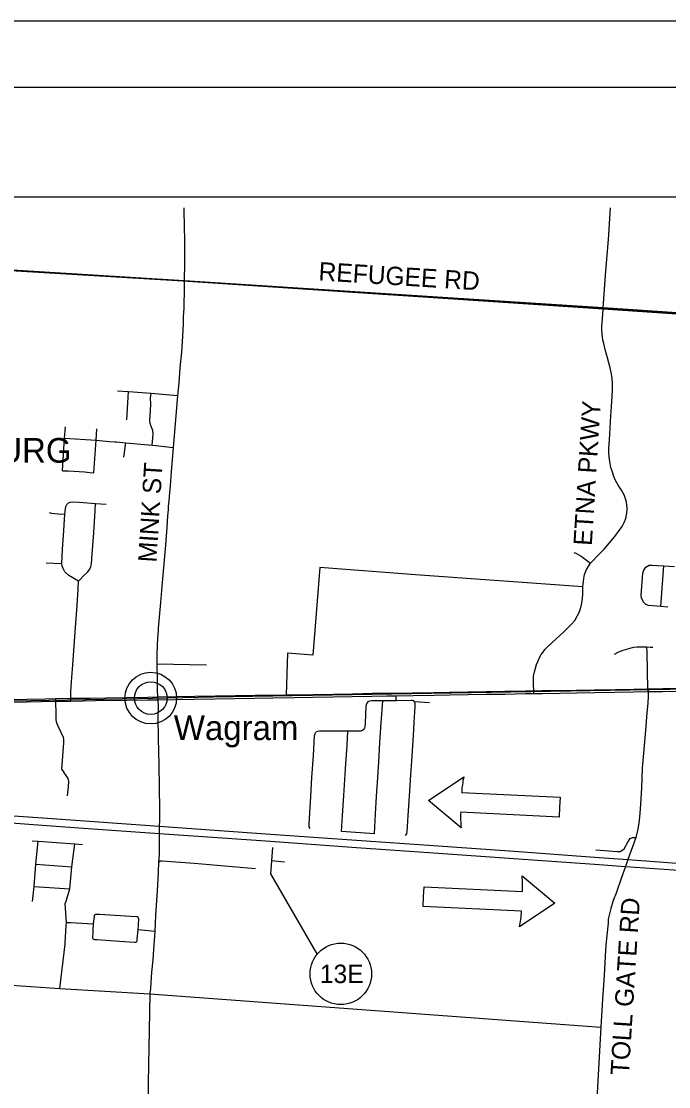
# Model space of a CAD drawing. Extents: x 1880545 to 1948545, y 79309 to 723051.
# Drawn here: x 1901899 to 1911747, y 706837 to 723051 of the extents above; entities that cross this region are included whole.
import ezdxf

# ---------------------------------------------------------------- set-up
doc = ezdxf.new("R2010")
doc.units = 0
for name, color, linetype in [('GM_X_Corporation', 7, 'Continuous'), ('GM_X_Corporation_Text', 7, 'Continuous'), ('GM_X_County_Road', 7, 'Continuous'), ('GM_X_Interstate_Route', 7, 'Continuous'), ('GM_X_Rail_Line', 7, 'Continuous'), ('GM_X_Township', 7, 'Continuous'), ('GM_X_Township_Road', 7, 'Continuous'), ('GM_X_Unincorporated', 7, 'Continuous'), ('GM_X_Unincorporated_Location', 7, 'Continuous'), ('GM_X_Unincorporated_Text', 7, 'Continuous'), ('GM_X_US_Route', 7, 'Continuous'), ('SH_Border', 7, 'Continuous'), ('SH_Cut_Line', 7, 'Continuous'), ('SH_Text', 7, 'Continuous')]:
    doc.layers.add(name, color=color, linetype=linetype)

msp = doc.modelspace()

# ---------------------------------------------------------------- linework, layer by layer
at = {"layer": 'GM_X_Corporation'}
msp.add_lwpolyline([(1919489, 720212), (1919365, 718089), (1918485, 718152), (1917525, 718232), (1914097, 718433), (1913810, 718462), (1910748, 718668), (1904355, 719098), (1898180, 719469), (1898145, 719477), (1897456, 719507), (1897439, 719506), (1897486, 720212)], dxfattribs=at)
at = {"layer": 'GM_X_County_Road'}
for points in [[(1904372, 720212), (1904373, 720143), (1904376, 719959), (1904380, 719685), (1904379, 719381), (1904378, 719096)], [(1904378, 719096), (1904377, 718914), (1904372, 718772), (1904370, 718687), (1904363, 718552), (1904359, 718449), (1904354, 718351), (1904344, 718172), (1904334, 718017), (1904312, 717776), (1904295, 717547), (1904276, 717358), (1904235, 716864), (1904211, 716564), (1904180, 716192), (1904161, 715980), (1904154, 715886), (1904148, 715813), (1904142, 715748), (1904135, 715674), (1904132, 715615), (1904124, 715524), (1904110, 715349), (1904100, 715213), (1904090, 715077), (1904082, 714967), (1904062, 714741), (1904037, 714449), (1904016, 714204), (1903986, 713870), (1903981, 713817), (1903978, 713770), (1903975, 713733), (1903970, 713647), (1903965, 713573), (1903963, 713522), (1903961, 713443), (1903960, 713361), (1903960, 713309), (1903960, 713270), (1903965, 713041), (1903966, 712877), (1903969, 712770), (1903973, 712727)], [(1903973, 712727), (1903978, 712618), (1903977, 712471), (1903979, 712132), (1903987, 711942), (1903993, 711730), (1903998, 711397), (1904003, 711057), (1904000, 710886), (1903998, 710801), (1903996, 710690), (1903994, 710365), (1903987, 710253), (1903980, 710101), (1903964, 709817), (1903941, 709446), (1903928, 709201), (1903905, 708856), (1903899, 708769), (1903881, 708580), (1903865, 708338), (1903856, 708249), (1903839, 707422), (1903835, 707192), (1903824, 706540)]]:
    msp.add_lwpolyline(points, dxfattribs=at)
at = {"layer": 'GM_X_Interstate_Route'}
for points in [[(1901417, 710877), (1902079, 710829), (1902917, 710765), (1903996, 710690), (1905616, 710577), (1906997, 710477), (1908167, 710395), (1909393, 710308), (1910617, 710222), (1911089, 710188), (1911973, 710126), (1913517, 710014), (1914784, 709928), (1915690, 709872), (1916454, 709820), (1916505, 709817), (1917219, 709770)], [(1901556, 710973), (1902367, 710916), (1903998, 710801), (1905618, 710687), (1906999, 710588), (1908169, 710506), (1909395, 710419), (1910619, 710332), (1911124, 710293), (1912007, 710228), (1913551, 710117), (1914818, 710030), (1915724, 709975), (1916510, 709920), (1917291, 709874), (1917321, 709872), (1918107, 709817), (1919464, 709729), (1920634, 709656), (1921054, 709629)]]:
    msp.add_lwpolyline(points, dxfattribs=at)
at = {"layer": 'GM_X_Rail_Line'}
msp.add_lwpolyline([(1889656, 712431), (1890757, 712458), (1898417, 712647), (1903434, 712741), (1904816, 712771), (1913576, 712916), (1914801, 712916), (1920019, 712995), (1921942, 713063), (1924553, 713124), (1928206, 713206)], dxfattribs=at)
at = {"layer": 'GM_X_Township'}
for points in [[(1919533, 720212), (1919387, 718085), (1918485, 718152), (1917525, 718232), (1914126, 718466), (1913826, 718485), (1910749, 718688), (1904377, 719099), (1899877, 719378), (1898145, 719477), (1897456, 719507), (1896834, 719533), (1896793, 719532), (1894775, 719644), (1893522, 719763), (1893081, 719771), (1891817, 719823), (1891843, 720212)], [(1899877, 719378), (1904377, 719099), (1910749, 718688), (1913826, 718485), (1914126, 718466), (1917525, 718232), (1918485, 718152), (1919387, 718085), (1922041, 717966)]]:
    msp.add_lwpolyline(points, dxfattribs=at)
at = {"layer": 'GM_X_Township_Road'}
for p, q in [((1903502, 716987), (1903529, 717418)), ((1903458, 716418), (1903491, 716637)), ((1902278, 714808), (1902514, 714797)), ((1911627, 714145), (1911672, 714765)), ((1903960, 713270), (1904715, 713258)), ((1907599, 712710), (1907600, 712786)), ((1907269, 710685), (1906771, 710721)), ((1902122, 710223), (1902665, 710182)), ((1902094, 709882), (1902639, 709846)), ((1903856, 708249), (1910713, 707744)), ((1910713, 707744), (1910640, 706422))]:
    msp.add_line(p, q, dxfattribs=at)
for points in [[(1910750, 718685), (1910787, 719189), (1910830, 719731), (1910864, 720212)], [(1904378, 719096), (1899878, 719375), (1898146, 719475)], [(1913827, 718483), (1910750, 718685), (1904378, 719096)], [(1909693, 712821), (1909693, 712863), (1909692, 712963), (1909691, 713086), (1909703, 713152), (1909721, 713208), (1909737, 713261), (1909760, 713319), (1909787, 713378), (1909808, 713415), (1909835, 713452), (1909865, 713489), (1909909, 713535), (1910152, 713760), (1910214, 713818), (1910264, 713869), (1910317, 713932), (1910357, 714007), (1910383, 714056), (1910400, 714101), (1910416, 714149), (1910424, 714194), (1910437, 714269), (1910441, 714331), (1910439, 714446), (1910454, 714571), (1910466, 714631), (1910495, 714708), (1910555, 714807), (1910690, 714941), (1910763, 715017), (1910848, 715116), (1910928, 715212), (1911010, 715320), (1911038, 715365), (1911069, 715422), (1911093, 715485), (1911110, 715567), (1911113, 715629), (1911109, 715697), (1911099, 715752), (1911070, 715844), (1911028, 715918), (1910979, 715992), (1910940, 716063), (1910914, 716124), (1910891, 716187), (1910869, 716260), (1910850, 716351), (1910841, 716422), (1910836, 716482), (1910837, 716553), (1910845, 716684), (1910868, 717049), (1910880, 717259), (1910893, 717436), (1910894, 717481), (1910893, 717544), (1910887, 717620), (1910877, 717681), (1910856, 717777), (1910815, 717929), (1910781, 718058), (1910758, 718147), (1910746, 718202), (1910735, 718290), (1910731, 718363), (1910732, 718421), (1910734, 718459), (1910749, 718665), (1910750, 718685)], [(1903364, 717427), (1903529, 717418), (1903874, 717390), (1904276, 717358)], [(1903891, 716598), (1903903, 716770), (1903899, 716823), (1903880, 716875), (1903864, 716915), (1903859, 716932), (1903857, 716947), (1903855, 716968), (1903855, 716995), (1903859, 717041), (1903871, 717220), (1903865, 717319), (1903874, 717390)], [(1902523, 716211), (1902558, 716707), (1902571, 716881)], [(1903003, 716180), (1903036, 716675), (1903047, 716848)], [(1902558, 716707), (1903036, 716675), (1903239, 716657), (1903321, 716650)], [(1903321, 716650), (1903345, 716649), (1903491, 716637), (1903891, 716598), (1903946, 716595), (1904211, 716564)], [(1902523, 716211), (1902616, 716209), (1902861, 716192), (1902943, 716186), (1903003, 716180)], [(1902769, 714529), (1902624, 714619), (1902560, 714675), (1902535, 714721), (1902522, 714757), (1902514, 714797), (1902524, 715012), (1902545, 715302), (1902561, 715552), (1902575, 715669), (1902591, 715698), (1902614, 715722), (1902641, 715735), (1902691, 715739), (1902778, 715731)], [(1902651, 712706), (1902650, 712748), (1902652, 712853), (1902669, 713063), (1902682, 713259), (1902696, 713476), (1902722, 713825), (1902747, 714161), (1902765, 714407), (1902769, 714529), (1902795, 714556), (1902852, 714618), (1902908, 714669), (1902941, 714714), (1902957, 714754), (1902967, 714795), (1902978, 714946), (1903001, 715267), (1903023, 715603), (1903028, 715712)], [(1902778, 715731), (1903028, 715712), (1903188, 715701)], [(1902321, 715575), (1902358, 715566), (1902461, 715555), (1902561, 715552)], [(1910306, 714966), (1910336, 714955), (1910372, 714938), (1910414, 714913), (1910555, 714807)], [(1910439, 714446), (1907893, 714627), (1906438, 714736), (1906335, 713405), (1905946, 713433), (1905927, 712801)], [(1911735, 714137), (1911627, 714145), (1911441, 714160), (1911400, 714176), (1911367, 714208), (1911331, 714271), (1911328, 714319), (1911354, 714651), (1911368, 714699), (1911400, 714742), (1911450, 714772), (1911489, 714776), (1911672, 714765), (1911835, 714756)], [(1910923, 713419), (1910987, 713456), (1911052, 713479), (1911091, 713489), (1911160, 713510), (1911213, 713526), (1911261, 713533), (1911314, 713533), (1911365, 713531), (1911414, 713533), (1911472, 713526), (1911505, 713524)], [(1911437, 712850), (1911432, 712891), (1911425, 713162), (1911420, 713449), (1911414, 713533)], [(1911437, 712850), (1911435, 712781), (1911427, 712676), (1911414, 712529), (1911392, 712257), (1911345, 711685), (1911333, 711386), (1911318, 711138)], [(1902421, 712744), (1902421, 712703), (1902423, 712508), (1902424, 712422), (1902429, 712393), (1902438, 712366), (1902453, 712331), (1902533, 712157), (1902541, 712121), (1902540, 712068), (1902512, 711669), (1902543, 711623)], [(1908110, 712680), (1907881, 712692), (1907869, 712707), (1907851, 712713), (1907831, 712715), (1907599, 712710), (1907399, 712708), (1907225, 712708), (1907193, 712705), (1907172, 712696), (1907154, 712676), (1907143, 712647), (1907139, 712613), (1907135, 712517), (1907129, 712354), (1907126, 712319), (1907120, 712296), (1907108, 712272), (1907089, 712256), (1907056, 712248), (1907004, 712248), (1906865, 712250), (1906433, 712250), (1906402, 712244), (1906381, 712234)], [(1907269, 710685), (1907289, 710991), (1907303, 711253), (1907323, 711545), (1907338, 711778), (1907355, 712074), (1907375, 712375), (1907399, 712708)], [(1907741, 710661), (1907761, 710683), (1907770, 710717), (1907784, 710959), (1907804, 711265), (1907825, 711585), (1907844, 711866), (1907865, 712183), (1907876, 712382), (1907892, 712621), (1907890, 712672), (1907881, 712692)], [(1906294, 710767), (1906279, 710790), (1906276, 710837), (1906288, 711007), (1906304, 711251), (1906320, 711542), (1906341, 711879), (1906361, 712176), (1906367, 712210), (1906381, 712234)], [(1906771, 710721), (1906786, 710963), (1906807, 711270), (1906831, 711673), (1906855, 712036), (1906865, 712250)], [(1902601, 711266), (1902617, 711403), (1902620, 711484), (1902611, 711525), (1902593, 711556), (1902543, 711623)], [(1911318, 711138), (1911310, 711002), (1911299, 710888), (1911277, 710758), (1911245, 710631), (1911218, 710543), (1911178, 710430), (1911124, 710293), (1911089, 710188), (1911025, 710003), (1910946, 709783), (1910903, 709673), (1910868, 709549), (1910848, 709470), (1910828, 709388), (1910824, 709324), (1910792, 708997), (1910791, 708986)], [(1902066, 710580), (1902153, 710572), (1902711, 710532), (1902830, 710523)], [(1902070, 709653), (1902094, 709882), (1902122, 710223), (1902153, 710572)], [(1902568, 709018), (1902580, 709296), (1902586, 709336), (1902568, 709627), (1902582, 709660), (1902597, 709710), (1902639, 709846), (1902665, 710182), (1902711, 710532)], [(1910636, 710442), (1910834, 710424), (1910962, 710415), (1911007, 710417), (1911036, 710429), (1911071, 710459), (1911126, 710560), (1911163, 710613), (1911198, 710629), (1911245, 710631)], [(1903987, 710253), (1904006, 710267), (1904022, 710272), (1904042, 710275), (1904530, 710241), (1905463, 710158)], [(1903928, 709201), (1903676, 709225), (1903681, 709307), (1903685, 709384), (1903683, 709401), (1903677, 709414), (1903661, 709420), (1903567, 709426), (1903089, 709459), (1903057, 709458), (1903028, 709458), (1903009, 709449), (1903005, 709426), (1903003, 709394), (1902994, 709313), (1902987, 709226), (1902985, 709159), (1902984, 709126), (1902982, 709100), (1902993, 709083), (1903012, 709078), (1903052, 709076), (1903394, 709051), (1903615, 709034), (1903645, 709035), (1903656, 709045), (1903660, 709057), (1903662, 709082), (1903676, 709225)], [(1902586, 709336), (1902649, 709335), (1902994, 709313)], [(1892142, 709082), (1893463, 708982), (1893651, 708968), (1894121, 708931), (1894267, 708922), (1895024, 708865), (1896101, 708804), (1896273, 708789), (1896426, 708776), (1896575, 708772), (1898149, 708664), (1901603, 708394), (1902483, 708331), (1903856, 708249)], [(1902483, 708331), (1902568, 709008), (1902568, 709018)], [(1910791, 708986), (1910784, 708916), (1910766, 708527), (1910739, 708170), (1910713, 707744)]]:
    msp.add_lwpolyline(points, dxfattribs=at)
at = {"layer": 'GM_X_Unincorporated'}
for radius in [393, 249]:
    msp.add_circle((1903868, 712751), radius, dxfattribs=at)
at = {"layer": 'GM_X_Unincorporated_Location'}
msp.add_line((1903868, 712751), (1903868, 712751), dxfattribs=at)
at = {"layer": 'GM_X_US_Route'}
for points in [[(1901704, 712732), (1901982, 712737), (1902260, 712741), (1902421, 712744), (1902650, 712748), (1902945, 712752), (1903187, 712756), (1903505, 712762), (1903820, 712767), (1903969, 712770), (1904247, 712774), (1904536, 712779), (1904853, 712784), (1905158, 712788), (1905457, 712794), (1905734, 712798), (1905927, 712801), (1906055, 712803), (1906338, 712808), (1906648, 712813), (1906939, 712818), (1907239, 712824), (1907468, 712827), (1907609, 712828), (1907850, 712832), (1908169, 712838), (1908412, 712842), (1908692, 712846), (1908973, 712850), (1909254, 712855), (1909570, 712860), (1909693, 712863), (1909818, 712865), (1910097, 712869), (1910340, 712873), (1910616, 712878), (1910936, 712883), (1911217, 712888), (1911432, 712891), (1911658, 712895), (1911977, 712899)], [(1901705, 712690), (1901985, 712695), (1902421, 712703), (1902651, 712706), (1903027, 712712), (1903506, 712720), (1903821, 712724), (1903973, 712727), (1904238, 712731), (1904528, 712736), (1904845, 712741), (1905149, 712746), (1905448, 712751), (1905726, 712755), (1906051, 712761), (1906330, 712765), (1906640, 712770), (1906931, 712776), (1907231, 712781), (1907460, 712784), (1907600, 712786), (1907858, 712790), (1908178, 712796), (1908418, 712800), (1908697, 712804), (1908976, 712809), (1909254, 712813), (1909567, 712819), (1909693, 712821), (1909826, 712823), (1910098, 712827), (1910349, 712831), (1910617, 712836), (1910925, 712840), (1911213, 712845), (1911437, 712850)], [(1911437, 712850), (1911655, 712852), (1911975, 712857), (1912254, 712861), (1912551, 712866), (1912855, 712870), (1912937, 712872)]]:
    msp.add_lwpolyline(points, dxfattribs=at)
at = {"layer": 'SH_Border'}
msp.add_lwpolyline([(1883545, 722051), (1947545, 722051), (1947545, 680051), (1883545, 680051)], close=True, dxfattribs=at)
at = {"layer": 'SH_Cut_Line'}
msp.add_lwpolyline([(1880545, 679051), (1948545, 679051), (1948545, 723051), (1880545, 723051)], close=True, dxfattribs=at)
at = {"layer": 'SH_Text'}
for p, q in [((1908091, 711190), (1908629, 711554)), ((1908590, 710775), (1908091, 711190)), ((1908597, 711315), (1910096, 711241)), ((1910096, 711241), (1910088, 711091)), ((1910081, 710941), (1908582, 711016)), ((1910088, 711091), (1910081, 710941)), ((1905721, 710477), (1905687, 710078)), ((1905704, 710277), (1905903, 710260)), ((1905687, 710078), (1906398, 708850)), ((1909516, 710048), (1910016, 709632)), ((1908018, 709731), (1908025, 709881)), ((1908025, 709881), (1909524, 709807)), ((1908011, 709581), (1908018, 709731)), ((1909509, 709507), (1908011, 709581)), ((1910016, 709632), (1909477, 709268))]:
    msp.add_line(p, q, dxfattribs=at)
msp.add_lwpolyline([(1884490, 720381), (1928141, 720381), (1928141, 691152), (1884490, 691152)], close=True, dxfattribs=at)
msp.add_circle((1906759, 708554), 468, dxfattribs=at)
for centre, start, end in [((1910096, 711241), 167.9363, 177.153), ((1910081, 710941), 177.153, 186.3696), ((1908025, 709881), 357.153, 6.3696), ((1908011, 709581), 347.9363, 357.153)]:
    msp.add_arc(centre, 1500, start, end, dxfattribs=at)

# ---------------------------------------------------------------- texts
at = {"layer": 'GM_X_Corporation_Text'}
msp.add_text('REYNOLDSBURG', height=375, rotation=0, dxfattribs=at).set_placement((1898455, 716334))
at = {"layer": 'GM_X_Unincorporated_Text'}
msp.add_text('Wagram', height=375, rotation=0, dxfattribs=at).set_placement((1904219, 712112))
at = {"layer": 'SH_Text'}
for s, rotation, p in [('REFUGEE RD', 356.4294, (1906414, 719109)), ('ETNA PKWY', 86.4008, (1910576, 715064)), ('MINK ST', 86.4008, (1903953, 714810)), ('TOLL GATE RD', 86.4008, (1911140, 707006))]:
    msp.add_text(s, height=280, rotation=rotation, dxfattribs=at).set_placement(p)
msp.add_text('13E', height=280, dxfattribs=at).set_placement((1906440, 708414))

doc.saveas('drawing.dxf')
